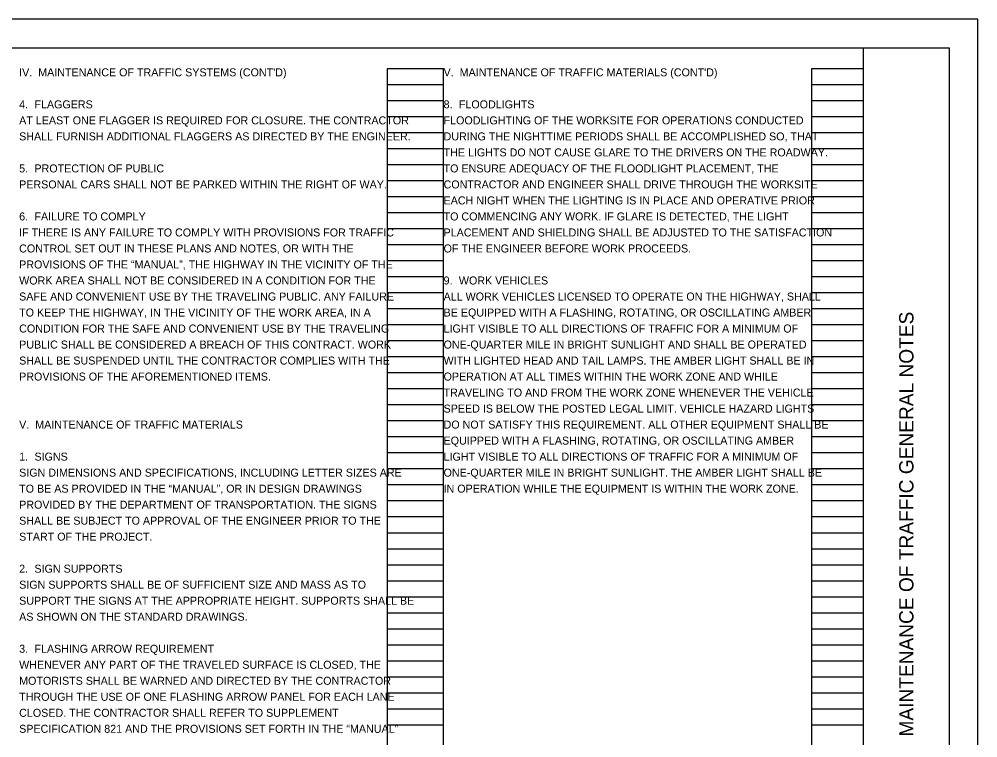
# Model space of a CAD drawing. Extents: x -15.1 to 34, y -7.8 to 43.8.
# Drawn here: x 17.24 to 34, y 9.43 to 22 of the extents above; entities that cross this region are included whole.
import ezdxf

# ---------------------------------------------------------------- set-up
doc = ezdxf.new("R2010")
doc.units = 0
for name, color, linetype in [('SH_Border', 7, 'Continuous'), ('SH_Cut_Line', 7, 'Continuous'), ('SH_Data', 7, 'Continuous'), ('SH_Text', 7, 'Continuous')]:
    doc.layers.add(name, color=color, linetype=linetype)

msp = doc.modelspace()

# ---------------------------------------------------------------- linework, layer by layer
at = {"layer": 'SH_Border'}
msp.add_line((32, 0.5), (32, 21.5), dxfattribs=at)
msp.add_lwpolyline([(1.5, 21.5), (33.5, 21.5), (33.5, 0.5), (1.5, 0.5)], close=True, dxfattribs=at)
at = {"layer": 'SH_Cut_Line'}
msp.add_lwpolyline([(0, 0), (34, 0), (34, 22), (0, 22)], close=True, dxfattribs=at)
at = {"layer": 'SH_Data'}
for p, q in [((23.68, 0.98), (23.68, 21.14)), ((23.68, 21.14), (24.66, 21.14)), ((24.66, 0.98), (24.66, 21.14)), ((31.1, 0.98), (31.1, 21.14)), ((31.1, 21.14), (32, 21.14)), ((32, 0.98), (32, 21.14)), ((23.68, 20.86), (24.66, 20.86)), ((31.1, 20.86), (32, 20.86)), ((23.68, 20.58), (24.66, 20.58)), ((31.1, 20.58), (32, 20.58)), ((23.68, 20.3), (24.66, 20.3)), ((31.1, 20.3), (32, 20.3)), ((23.68, 20.02), (24.66, 20.02)), ((31.1, 20.02), (32, 20.02)), ((23.68, 19.74), (24.66, 19.74)), ((31.1, 19.74), (32, 19.74)), ((23.68, 19.46), (24.66, 19.46)), ((31.1, 19.46), (32, 19.46)), ((23.68, 19.18), (24.66, 19.18)), ((31.1, 19.18), (32, 19.18)), ((23.68, 18.9), (24.66, 18.9)), ((31.1, 18.9), (32, 18.9)), ((23.68, 18.62), (24.66, 18.62)), ((31.1, 18.62), (32, 18.62)), ((23.68, 18.34), (24.66, 18.34)), ((31.1, 18.34), (32, 18.34)), ((23.68, 18.06), (24.66, 18.06)), ((31.1, 18.06), (32, 18.06)), ((23.68, 17.78), (24.66, 17.78)), ((31.1, 17.78), (32, 17.78)), ((23.68, 17.5), (24.66, 17.5)), ((31.1, 17.5), (32, 17.5)), ((23.68, 17.22), (24.66, 17.22)), ((31.1, 17.22), (32, 17.22)), ((23.68, 16.94), (24.66, 16.94)), ((31.1, 16.94), (32, 16.94)), ((23.68, 16.66), (24.66, 16.66)), ((31.1, 16.66), (32, 16.66)), ((23.68, 16.38), (24.66, 16.38)), ((31.1, 16.38), (32, 16.38)), ((23.68, 16.1), (24.66, 16.1)), ((31.1, 16.1), (32, 16.1)), ((23.68, 15.82), (24.66, 15.82)), ((31.1, 15.82), (32, 15.82)), ((23.68, 15.54), (24.66, 15.54)), ((31.1, 15.54), (32, 15.54)), ((23.68, 15.26), (24.66, 15.26)), ((31.1, 15.26), (32, 15.26)), ((23.68, 14.98), (24.66, 14.98)), ((31.1, 14.98), (32, 14.98)), ((23.68, 14.7), (24.66, 14.7)), ((31.1, 14.7), (32, 14.7)), ((23.68, 14.42), (24.66, 14.42)), ((31.1, 14.42), (32, 14.42)), ((23.68, 14.14), (24.66, 14.14)), ((31.1, 14.14), (32, 14.14)), ((23.68, 13.86), (24.66, 13.86)), ((31.1, 13.86), (32, 13.86)), ((23.68, 13.58), (24.66, 13.58)), ((31.1, 13.58), (32, 13.58)), ((23.68, 13.3), (24.66, 13.3)), ((31.1, 13.3), (32, 13.3)), ((23.68, 13.02), (24.66, 13.02)), ((31.1, 13.02), (32, 13.02)), ((23.68, 12.74), (24.66, 12.74)), ((31.1, 12.74), (32, 12.74)), ((23.68, 12.46), (24.66, 12.46)), ((31.1, 12.46), (32, 12.46)), ((23.68, 12.18), (24.66, 12.18)), ((31.1, 12.18), (32, 12.18)), ((23.68, 11.9), (24.66, 11.9)), ((31.1, 11.9), (32, 11.9)), ((23.68, 11.62), (24.66, 11.62)), ((31.1, 11.62), (32, 11.62)), ((23.68, 11.34), (24.66, 11.34)), ((31.1, 11.34), (32, 11.34)), ((23.68, 11.06), (24.66, 11.06)), ((31.1, 11.06), (32, 11.06)), ((23.68, 10.78), (24.66, 10.78)), ((31.1, 10.78), (32, 10.78)), ((23.68, 10.5), (24.66, 10.5)), ((31.1, 10.5), (32, 10.5)), ((23.68, 10.22), (24.66, 10.22)), ((31.1, 10.22), (32, 10.22)), ((23.68, 9.94), (24.66, 9.94)), ((31.1, 9.94), (32, 9.94)), ((23.68, 9.66), (24.66, 9.66)), ((31.1, 9.66), (32, 9.66))]:
    msp.add_line(p, q, dxfattribs=at)

# ---------------------------------------------------------------- texts
msp.add_text('MAINTENANCE OF TRAFFIC GENERAL NOTES', height=0.25, rotation=90, dxfattribs=at).set_placement((32.875, 9.455))
at = {"layer": 'SH_Text'}
for s, p in [("IV.  MAINTENANCE OF TRAFFIC SYSTEMS (CONT'D)", (17.24, 21)), ("V.  MAINTENANCE OF TRAFFIC MATERIALS (CONT'D)", (24.66, 21)), ('4.  ', (17.24, 20.44)), ('FLAGGERS', (17.507, 20.44)), ('8.  ', (24.66, 20.44)), ('FLOODLIGHTS', (24.927, 20.44)), ('AT LEAST ONE FLAGGER IS REQUIRED FOR CLOSURE. THE CONTRACTOR ', (17.24, 20.16)), ('FLOODLIGHTING OF THE WORKSITE FOR OPERATIONS CONDUCTED ', (24.66, 20.16)), ('SHALL FURNISH ADDITIONAL FLAGGERS AS DIRECTED BY THE ENGINEER. ', (17.24, 19.88)), ('DURING THE NIGHTTIME PERIODS SHALL BE ACCOMPLISHED SO, THAT ', (24.66, 19.88)), ('THE LIGHTS DO NOT CAUSE GLARE TO THE DRIVERS ON THE ROADWAY. ', (24.66, 19.6)), ('5.  ', (17.24, 19.32)), ('PROTECTION OF PUBLIC', (17.507, 19.32)), ('TO ENSURE ADEQUACY OF THE FLOODLIGHT PLACEMENT, THE ', (24.66, 19.32)), ('PERSONAL CARS SHALL NOT BE PARKED WITHIN THE RIGHT OF WAY.', (17.24, 19.04)), ('CONTRACTOR AND ENGINEER SHALL DRIVE THROUGH THE WORKSITE ', (24.66, 19.04)), ('EACH NIGHT WHEN THE LIGHTING IS IN PLACE AND OPERATIVE PRIOR ', (24.66, 18.76)), ('6.  ', (17.24, 18.48)), ('FAILURE TO COMPLY', (17.507, 18.48)), ('TO COMMENCING ANY WORK. IF GLARE IS DETECTED, THE LIGHT ', (24.66, 18.48)), ('IF THERE IS ANY FAILURE TO COMPLY WITH PROVISIONS FOR TRAFFIC ', (17.24, 18.2)), ('PLACEMENT AND SHIELDING SHALL BE ADJUSTED TO THE SATISFACTION ', (24.66, 18.2)), ('CONTROL SET OUT IN THESE PLANS AND NOTES, OR WITH THE ', (17.24, 17.92)), ('OF THE ENGINEER BEFORE WORK PROCEEDS. ', (24.66, 17.92)), ('PROVISIONS OF THE “MANUAL”, THE HIGHWAY IN THE VICINITY OF THE ', (17.24, 17.64)), ('WORK AREA SHALL NOT BE CONSIDERED IN A CONDITION FOR THE ', (17.24, 17.36)), ('9.  ', (24.66, 17.36)), ('WORK VEHICLES', (24.927, 17.36)), ('SAFE AND CONVENIENT USE BY THE TRAVELING PUBLIC. ANY FAILURE ', (17.24, 17.08)), ('ALL WORK VEHICLES LICENSED TO OPERATE ON THE HIGHWAY, SHALL ', (24.66, 17.08)), ('TO KEEP THE HIGHWAY, IN THE VICINITY OF THE WORK AREA, IN A ', (17.24, 16.8)), ('BE EQUIPPED WITH A FLASHING, ROTATING, OR OSCILLATING AMBER ', (24.66, 16.8)), ('CONDITION FOR THE SAFE AND CONVENIENT USE BY THE TRAVELING ', (17.24, 16.52)), ('LIGHT VISIBLE TO ALL DIRECTIONS OF TRAFFIC FOR A MINIMUM OF ', (24.66, 16.52)), ('PUBLIC SHALL BE CONSIDERED A BREACH OF THIS CONTRACT. WORK ', (17.24, 16.24)), ('ONE-QUARTER MILE IN BRIGHT SUNLIGHT AND SHALL BE OPERATED ', (24.66, 16.24)), ('SHALL BE SUSPENDED UNTIL THE CONTRACTOR COMPLIES WITH THE ', (17.24, 15.96)), ('WITH LIGHTED HEAD AND TAIL LAMPS. THE AMBER LIGHT SHALL BE IN ', (24.66, 15.96)), ('PROVISIONS OF THE AFOREMENTIONED ITEMS. ', (17.24, 15.68)), ('OPERATION AT ALL TIMES WITHIN THE WORK ZONE AND WHILE ', (24.66, 15.68)), ('TRAVELING TO AND FROM THE WORK ZONE WHENEVER THE VEHICLE ', (24.66, 15.4)), ('SPEED IS BELOW THE POSTED LEGAL LIMIT. VEHICLE HAZARD LIGHTS ', (24.66, 15.12)), ('V.  MAINTENANCE OF TRAFFIC MATERIALS', (17.24, 14.84)), ('DO NOT SATISFY THIS REQUIREMENT. ALL OTHER EQUIPMENT SHALL BE ', (24.66, 14.84)), ('EQUIPPED WITH A FLASHING, ROTATING, OR OSCILLATING AMBER ', (24.66, 14.56)), ('1.  ', (17.24, 14.28)), ('SIGNS', (17.507, 14.28)), ('LIGHT VISIBLE TO ALL DIRECTIONS OF TRAFFIC FOR A MINIMUM OF ', (24.66, 14.28)), ('SIGN DIMENSIONS AND SPECIFICATIONS, INCLUDING LETTER SIZES ARE ', (17.24, 14)), ('ONE-QUARTER MILE IN BRIGHT SUNLIGHT. THE AMBER LIGHT SHALL BE ', (24.66, 14)), ('TO BE AS PROVIDED IN THE “MANUAL”, OR IN DESIGN DRAWINGS ', (17.24, 13.72)), ('IN OPERATION WHILE THE EQUIPMENT IS WITHIN THE WORK ZONE.', (24.66, 13.72)), ('PROVIDED BY THE DEPARTMENT OF TRANSPORTATION. THE SIGNS ', (17.24, 13.44)), ('SHALL BE SUBJECT TO APPROVAL OF THE ENGINEER PRIOR TO THE ', (17.24, 13.16)), ('START OF THE PROJECT. ', (17.24, 12.88)), ('2.  ', (17.24, 12.32)), ('SIGN SUPPORTS', (17.507, 12.32)), ('SIGN SUPPORTS SHALL BE OF SUFFICIENT SIZE AND MASS AS TO ', (17.24, 12.04)), ('SUPPORT THE SIGNS AT THE APPROPRIATE HEIGHT. SUPPORTS SHALL BE ', (17.24, 11.76)), ('AS SHOWN ON THE STANDARD DRAWINGS. ', (17.24, 11.48)), ('3.  ', (17.24, 10.92)), ('FLASHING ARROW REQUIREMENT', (17.507, 10.92)), ('WHENEVER ANY PART OF THE TRAVELED SURFACE IS CLOSED, THE ', (17.24, 10.64)), ('MOTORISTS SHALL BE WARNED AND DIRECTED BY THE CONTRACTOR ', (17.24, 10.36)), ('THROUGH THE USE OF ONE FLASHING ARROW PANEL FOR EACH LANE ', (17.24, 10.08)), ('CLOSED. THE CONTRACTOR SHALL REFER TO SUPPLEMENT ', (17.24, 9.8)), ('SPECIFICATION 821 AND THE PROVISIONS SET FORTH IN THE “MANUAL” ', (17.24, 9.52))]:
    msp.add_text(s, height=0.14, dxfattribs=at).set_placement(p)

doc.saveas('drawing.dxf')
